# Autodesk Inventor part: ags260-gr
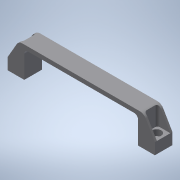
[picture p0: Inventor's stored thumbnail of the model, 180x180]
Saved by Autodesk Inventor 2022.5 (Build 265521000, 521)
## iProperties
Created: 2016-12
Part Number: ags260-gr
Material: 一般
Document SubType Name: Modeling
Designer: imaocorp
Density: 1 g/cm^3
Appearance: 既定
Author: imaocorp
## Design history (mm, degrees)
node "ags260-gr.x_t1"
node "ags260-gr"
node "Base1"
